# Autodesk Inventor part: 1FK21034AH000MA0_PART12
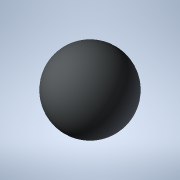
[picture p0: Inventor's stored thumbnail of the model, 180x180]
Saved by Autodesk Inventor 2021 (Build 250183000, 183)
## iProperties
Created: 2025-04
Part Number: 1FK21034AH000MA0_PART12
Material: Generic
Catalog Web Link: www.3dfindit.com
Description: -Servo synchronous motor
Document SubType Name: Modeling
Designer: psAdmin
Mass: 0.113097 g
Surface Area: 1.13097 cm^2
Volume: 0.113097 cm^3
Density: 1 g/cm^3
Appearance: PSOLRGB-212-217-219
Category: PARTsolutions
Title: 1FK21034AH000MA0_PART12
Author: Cadenas PARTsolutions
Comments: Servo synchronous motor
Sending System: PARTsolutions
Preprocessor: ST-DEVELOPER v19.3
PSOL_IDENT_0: {$CADENAS_DATA/23d-libs/siemens_ag/_cat_/ec/b7/1fk21034ah000ma0.prj},216 {VTYP=3D},{NB=1FK21034AH000
PSOL_IDENT_1: MA0_PART12},{LINA=1FK21034AH000MA0_PART12},{NN=1FK21034AH000MA0_PART12},{NOPRJ=TRUE},{DATE=19.08.202
PSOL_IDENT_2: 5 14:01:05},{GEOMDATE=30.07.2025 02:01:02},{VERSION=},{LINEID=10},{WBVAR=},{WBNUMERIC=}  {NB=1FK2103
PSOL_IDENT_3: 4AH000MA0_PART12},{LINA=1FK21034AH000MA0_PART12},{KT=DUMMY},{PREVIEW=../../../_pool_/7c/50/p_d211_xx
PSOL_IDENT_4: _00932j.png},{DESCSHORT=SIMOTICS S-1FK2 HD, SINAMICS S210 3AC 400V-480V, 1.01 Nm, 4500 rpm},{DESCLON
PSOL_IDENT_5: G=SIMOTICS S-1FK2 HD servo motor M0=1.27 Nm; PN = 0.48 kW at nN=4500 rpm (380-480 V); PN = 0.3 kW at
PSOL_IDENT_6: nN=2500 rpm (200-240 V); degree of protection IP64; cylindrical shaft D14 x 30 mm; absolute encoder
PSOL_IDENT_7: 22-bit + 12-bit multiturn (encoder AM22DQC); with OCC interface; plug size M17, rotatable; SIMOTICS
PSOL_IDENT_8: S-1FK2 servomotorfor a wide range of uses in industrial environments. SIMOTICS S‑1FK2 servomotors a
PSOL_IDENT_9: re compact synchronous motors with a high dynamic performance that set themselves apart as a result
PSOL_IDENT_10: of their high power density, degree of protection and overload capability. The motors are available
PSOL_IDENT_11: in two variants: as High Dynamic variant (highest dynamic performance as a result of the low intrins
PSOL_IDENT_12: ic moment of inertia for applications demanding a high dynamic performance with low moved masses) -
PSOL_IDENT_13: and as Compact variant (precise and stable closed-loop control for medium up to large moved masses a
PSOL_IDENT_14: s a result of a medium intrinsic moment of inertia). SIMOTICSS‑1FK2 servomotors fully exploit their
PSOL_IDENT_15: strengths in a system with the SINAMICSS210 frequency converter and simple connection using the one
PSOL_IDENT_16: cable connection (OCC). Advantages include the short control and positioning times, fast and precise
PSOL_IDENT_17: correction of disturbing quantities as well as stable control with a high dynamic performance. The
PSOL_IDENT_18: servo motors can be configured to address a wide range of requirements. For example with and without
PSOL_IDENT_19: holding brake, IP64 or IP65 degree of protection, singleturn or multiturn absolute encoders - to na
PSOL_IDENT_20: me just a few. Further, the servomotors are available in different shaft heights extending from 20 t
PSOL_IDENT_21: o 100. A shaft sealing ring is available to achieve an IP65 degree of protection and for subsequent
PSOL_IDENT_22: mounting at the motor or as spare part. SIMOTICS - the optimum motor for each and every motion contr
PSOL_IDENT_23: ol application.},{INTNO=4034106444822},{SUPPLIERALTNO=1FK2103-4AH00-0MA0},{MANUID=1FK21034AH000MA0},
PSOL_IDENT_24: {MANUNAME=Siemens},{MANUTYPEDESC=SYNCHRONOUS MOTOR 1FK2 HD 1,27 NM},{AAU732=SIMOTICS},{AAO057=S-1FK2
PSOL_IDENT_25: },{AAU734=SIMOTICS S-1FK2 HD servo motor M0=1.27 Nm; PN = 0.48 kW at nN=4500 rpm (380-480 V); PN = 0
PSOL_IDENT_26: .3 kW at nN=2500 rpm (200-240 V); degree of protection IP64; cylindrical shaft D14 x 30 mm; absolute
PSOL_IDENT_27: encoder 22-bit + 12-bit multiturn (encoder AM22DQC); with OCC interface; plug size M17, rotatable;}
PSOL_IDENT_28: ,{AAW338=SYNCHRONOUS MOTOR 1FK2 HD 1,27 NM},{AAO742=SIMOTICS},{AAO663=4034106444822},{NOCUPEROU=1},{
PSOL_IDENT_29: PRICEQUANTITY=1},{QUANTITYMIN=1},{QUANTITYINT=1},{CTN=85015100},{COO=RO},{AAO676=1FK2103-4AH00-0MA0}
PSOL_IDENT_30: ,{AAO677=Siemens AG},{ORDERUNIT=C62},{CONTENTUNIT=C62}
NB: 1FK21034AH000MA0_PART12
NT: Servo synchronous motor
NBSYN: $MANUID._PART12
LINA: 1FK21034AH000MA0_PART12
CATALOG: SIEMENS
PREVIEW: ../../../_pool_/7c/50/p_d211_xx_00932j.png
DESCSHORT: SIMOTICS S-1FK2 HD, SINAMICS S210 3AC 400V-480V, 1.01 Nm, 4500 rpm
DESCLONG: SIMOTICS S-1FK2 HD servo motor M0=1.27 Nm; PN = 0.48 kW at nN=4500 rpm (380-480 V); PN = 0.3 kW at nN=2500 rpm (200-240 V); degree of protection IP64; cylindric
INTNO: 4034106444822
SUPPLIERALTNO: 1FK2103-4AH00-0MA0
MANUID: 1FK21034AH000MA0
MANUNAME: Siemens
MANUTYPEDESC: SYNCHRONOUS MOTOR 1FK2 HD 1,27 NM
AAU732: SIMOTICS
AAO057: S-1FK2
AAU734: SIMOTICS S-1FK2 HD servo motor M0=1.27 Nm; PN = 0.48 kW at nN=4500 rpm (380-480 V); PN = 0.3 kW at nN=2500 rpm (200-240 V); degree of protection IP64; cylindric
AAW338: SYNCHRONOUS MOTOR 1FK2 HD 1,27 NM
AAO742: SIMOTICS
AAO663: 4034106444822.0
NOCUPEROU: 1
PRICEQUANTITY: 1
QUANTITYMIN: 1
QUANTITYINT: 1
CTN: 85015100
COO: RO
ARTICLENO: 1FK21034AH000MA0_PART12
BOMINFO: 1FK21034AH000MA0_PART12
CREATOR: CADENAS GmbH
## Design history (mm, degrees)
feature "2025_04_17_15_01_37_0314"
body "Solid1"
